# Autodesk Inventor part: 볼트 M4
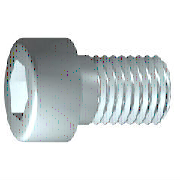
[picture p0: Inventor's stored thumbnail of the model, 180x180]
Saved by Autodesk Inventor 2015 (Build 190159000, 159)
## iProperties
IsCustomPart: 0
Created: 2018-09
Part Number: 볼트 M4
Material: 스테인리스강
Description: 6각머리 태핑 나사
Document SubType Name: Modeling
Standard: KS B 1003
Standards Organization: KS
Language: ko-KR
Size Designation: M 4 x 10
Categories: <MemberInstance><Categories><Category DisplayName="조임쇠" InternalName="e4da775c-781d-43d5-af7c-5136215cf5a6" Mnemonic="FSTN"><Category DisplayName="볼트" InternalN
Density: 1 g/cm^3
Appearance: 반광택
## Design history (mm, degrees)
sketch "스케치1"
  geometry: L1 (-1, 0)-(10, 0); L2 (10, 0)-(10, 2); L3 (10, 2)-(1.75, 2); L4 (1.75, 2)-(1.32, 2); L5 (1.32, 2)-(0, 2); L6 (0, 2)-(0, 3.5); L7 (0, 3.5)-(-4, 3.5); L8 (-4, 3.5)-(-4, 1.732); L9 (-4, 1.732)-(-2, 1.732); L10 (-2, 1.732)-(-1, 0); L11 (-6.8, 0)-(12.8, 0) reference; L12 (0, -0.7)-(0, 4.2) reference; L13 (1.75, 2)-(0, 2)
  constraints: 22 end point, 6 parallel, 2 collinear, 2 perpendicular, 1 horizontal, 1 point on line
  dimensions: "d1" = 8.25 distance from line of L3.end L2 (= GEL); "d2" = 0.42952 distance of L4.end L3.end (computed from GAL); "d3" = 4 distance between parallel lines of L8 L6 (= KOH); "d4" = 2 distance of L8.end L9.end (= INTI); "d5" = 60 deg angle of L10 L1; "d6" = 4 diameter of L3 L1 (= GD); "d7" = 4 diameter of L5 L1 (= BDM); "d8" = 3.4641 diameter of L9 L1 (= 1.1547 x SW); "d9" = 7 diameter of L7 L1 (= KOD); "d26" = 10 distance between parallel lines of L12 L2 (= NLG)
revolve "본체" sketch "스케치1" stored, may be unused: angle "d10" = 90 deg
sketch "스케치2"
  geometry: L1 (0, -4.9)-(0, 4.9) reference; L2 (-4.9, 0)-(4.9, 0) reference; L3 (1.732, 0)-(0.866, -1.5); L4 (0.866, -1.5)-(-0.866, -1.5); L5 (-0.866, -1.5)-(-1.732, 0); L6 (-1.732, 0)-(-0.866, 1.5); L7 (-0.866, 1.5)-(0.866, 1.5); L8 (0.866, 1.5)-(1.732, 0); 2 further points
  constraints: 12 end point, 1 coincident, 1 horizontal alignment, 1 point on line, 12 other
extrude "슬롯" join sketch "스케치2" stored distance "d11" = 10; taper "d12" = 0 deg
workplane "Work Plane1"
fillet "Fillet2" dims "d30" = 0.1 (= R)
body "Solid1"
fillet "모깎기1" dims "d17" = 0.4 (= RR)
feature "스레드" dims "d13" = 8.25 (= GEL), "d14" = 0
chamfer "모따기1" distance "d15" = 0.42941 (= -0.5 x SPD + 0.5 x GD); stored, may be unused: second distance "d16" = 0.42941 (= GUL), angle "d27" = 45 deg
other parameters: "GD" = 4 (= NND) [user parameter; used in 2 equation terms], "NLG" = 10 [user parameter; used in 1 equation term], "GEL" = 8.25 [user parameter; used in 2 equation terms], "KOD" = 7 [user parameter; used in 1 equation term], "KOH" = 4 [user parameter; used in 1 equation term], "INTI" = 2 [user parameter; used in 1 equation term], "GAL" = 0.42941 (= 0.61345 x PTC) [user parameter; used in 1 equation term], "GUL" = 0.42941 (= 0.61345 x PTC) [user parameter; used in 1 equation term], "BDM" = 4 (= NND) [user parameter; used in 1 equation term], "SW" = 3 [user parameter; used in 2 equation terms], "RR" = 0.4 [user parameter; used in 1 equation term], "SPD" = 3.14117 (= NND - 1.2269 x PTC) [user parameter; used in 1 equation term], "d19" = 0, "d28" = 0, "d29" = 0, "R" = 0.1 [user parameter; used in 1 equation term], "PHH" = 0.2 [user parameter], "GD1" = 3.14117 (= THREADDIA - 1.2269 x PTC) [user parameter], "THREADDIA" = 4 [user parameter; used in 1 equation term], "FAWI" = 45 deg [user parameter], "TPU" = 14.28571 (computed from PTC) [user parameter], "PTC" = 0.7 [user parameter; used in 5 equation terms], "NND" = 4 [user parameter; used in 3 equation terms], "TOA" = 30 deg [user parameter], "E0" = 3.465 (= 1.155 x SW) [user parameter]
